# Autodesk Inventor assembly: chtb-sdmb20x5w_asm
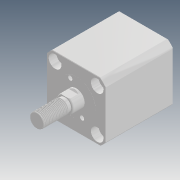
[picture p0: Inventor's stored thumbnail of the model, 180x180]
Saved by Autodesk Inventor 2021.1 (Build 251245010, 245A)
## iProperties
Company: Microsoft
Created: 2018-05
Part Number: chtb-sdmb20x5w_asm
Description: STEP AP214
Document SubType Name: Assembly
Designer: user
Title: chtb-sdmb20x5w_asm.STEP
Author: Windows
Revision Number: ÈÎºÎ
Sending System: SolidWorks 2015
Preprocessor: SwSTEP 2.0
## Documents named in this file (4)
- D:\Vault_2016\Projekty\Clamptek\Hydraulic\CHTB\CHTB-20\Inventor\CHTB-SDMB20x5W\chtb-sdmb20x5w_asm.iam
- D:\Vault_2016\Projekty\Clamptek\Hydraulic\CHTB\CHTB-20\Inventor\CHTB-SDMB20x5W\CHTB-SDMB20X5NBT.ipt
- D:\Vault_2016\Projekty\Clamptek\Hydraulic\CHTB\CHTB-20\Inventor\CHTB-SDMB20x5W\CHTB-SDMB20X5WHSG.ipt
- D:\Vault_2016\Projekty\Clamptek\Hydraulic\CHTB\CHTB-20\Inventor\CHTB-SDMB20x5W\QG_3.ipt
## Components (3 placed, 3 different names)
1. CHTB-SDMB20X5NBT_1
2. CHTB-SDMB20X5WHSG_2
3. QG_3_3
